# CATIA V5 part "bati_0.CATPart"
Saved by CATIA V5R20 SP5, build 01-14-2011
Part number: bati_0
Publications: "largeur_barre_7", "x_hauteur", "épaisseur bati"
Bounding box of the stored display mesh (mm): x -70 to 110, y -137 to 15, z 0 to 249.913
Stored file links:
  M:\EU_thinkMotion\IAO_2010\iao\IAO_MMS_Groupe2\IAO_MMS_Groupe2\sdubois\sdubois\sdubois\IAO_mecanisme\bati_0.CATPart
  M:\EU_thinkMotion\IAO_2010\iao\IAO_MMS_Groupe2\IAO_MMS_Groupe2\sdubois\sdubois\sdubois\IAO_mecanisme\assembage final.CATProduct
  M:\EU_thinkMotion\IAO_2010\iao\IAO_MMS_Groupe2\IAO_MMS_Groupe2\sdubois\sdubois\sdubois\IAO_mecanisme\squelette_bati.CATPart
  C:\Users\User\Desktop\IAO mécanisme\ancien\bati.CATPart
  M:\EU_thinkMotion\IAO_2010\iao\IAO_MMS_Groupe2\IAO_MMS_Groupe2\sdubois\sdubois\sdubois\IAO_mecanisme\squelette_7.CATPart
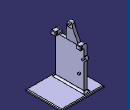
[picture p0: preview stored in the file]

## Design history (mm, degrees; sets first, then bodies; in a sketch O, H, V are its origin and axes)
Parameters
  largeur_barre = 6 mm
  x_hauteur = 20 mm
  `épaisseur bati` = 12 mm
External parameters (linked from other documents)
  `External.diamètre pivot en D` = 8 mm
  `External.diamètre pivot en A` = 8 mm
  `External.diamètre pivot en H` = 8 mm
Set1
  Plane1 to Plane5: linked copy from another document
  Point1 to Point3: linked copy from another document
  Plane6: linked copy from another document
  Plane7: linked copy from another document
  Point4: linked copy from another document
Body1 (main body)
  Sketch1 on Plane1, origin (0, 0, 0), H (0, 1, 0), V (0, 0, 1)
    line L1 (-137, 0) -> (15, 0)
    line L2 (-137, 0) -> (-137, 8)
    line L3 (-137, 8) -> (-122, 8)
    line L4 (0, 8) -> (15, 8)
    line L5 (15, 8) -> (15, 0)
    construction line L6 through (-77.2527, 0) direction (1, 0)
    line L7 (-122, 168) -> (-76, 168)
    line L8 (0, 168) -> (-22, 168)
    line L9 (0, 8) -> (0, 168)
    arc A1 centre (-49, 240) radius 10 from (-58.6074, 242.7746) to (-39.6859, 243.6397) cw
    point P1 (-22, 168)
    point P2 (-22, 168)
    line L10 (-122, 8) -> (-122, 168)
    point P3 (-49, 240)
    point P4 (0, 0)
    construction line L11 through (0, 0) direction (0, 1)
    line L12 (-22, 168) -> (-39.6859, 243.6397)
    line L13 (-76, 168) -> (-58.6074, 242.7746)
    reference intersected line E1 through (0, 0) direction (0, 1) from Plane2
    reference intersected line E2 through (0, 0) direction (-1, 0) from Plane3
    reference intersected line E3 through (0, 0) direction (-1, 0) from Plane3
    length L1 = 152
    length L2 = 8
    length L3 = 15
    length L4 = 15
    length L5 = 8
    distance L1 L6 = 0
    length L7 = 46
    length L8 = 22
    angle L4 L5 = 90
    angle L5 L1 = 90
    radius A1 = 10
    distance P2 P1 = 0
    angle L2 L3 = 90
    angle L2 L1 = 90
    angle L10 L3 = 90
    distance P3 L1 = 240 {= 220mm+x_hauteur}
    distance L8 L1 = 168 {= 148mm+x_hauteur}
    distance L7 L1 = 168 {= 148mm+x_hauteur}
    distance P3 L9 = 49
    distance E1 L9 = 0
    distance E2 L1 = 0
    parallelism: L7 L8, L8 E3
  Sketch2 on Plane2, origin (0, 0, 0), H (-1, 0, 0), V (0, 0, 1)
    line L1 (70, 8) -> (70, 0)
    line L2 (-110, 0) -> (70, 0)
    line L3 (0, 8) -> (-110, 8)
    line L4 (0, 168) -> (0, 8)
    line L5 (12, 8) -> (12, 168)
    line L6 (-12, 250) -> (-12, 228)
    line L7 (0, 228) -> (0, 250)
    line L8 (-110, 8) -> (-110, 0)
    line L9 (-12, 250) -> (0, 250)
    construction line L10 through (0, 0) direction (1, 0)
    construction line L11 through (0, 0) direction (0, 1)
    line L12 (70, 8) -> (12, 8)
    line L13 (12, 168) -> (0, 228)
    line L14 (-12, 228) -> (0, 168)
    reference intersected line E1 through (0, 0) direction (0, -1) from Plane1
    reference intersected line E2 through (0, 0) direction (-1, 0) from Plane3
    length L1 = 8
    distance L3 L2 = 8
    distance L5 L4 = 12 {= `épaisseur bati`}
    length L6 = 22
    length L5 = 160 {= 140mm+x_hauteur}
    length L4 = 160 {= 140mm+x_hauteur}
    distance L6 L4 = 12 {= 2*largeur_barre}
    distance L7 L5 = 12 {= 2*largeur_barre}
    distance L4 L8 = 110
    distance L9 L2 = 250 {= 230mm+x_hauteur}
    distance L1 L8 = 180
    length L7 = 22
    distance L4 E1 = 0
    distance L2 E2 = 0
    parallelism: L14 L13
  SolidCombine1: FirstComponentDirection Sketch2, FirstComponentProfile Sketch2, SecondComponentDirection Sketch1, SecondComponentProfile Sketch1
  Sketch3 on face of SolidCombine1 from Sketch2.L4, origin (0, 0, 0), H (0, 1, 0), V (0, 0, 1)
    point P1 (0, 138.775)
    point P2 (0, 121.225)
    point P3 (-2, 130)
    arc A1 centre (-2, 130) radius 9 from (0, 138.775) to (0, 121.225) cw
    point P4 (0, 138.775)
    point P5 (0, 121.225)
    line L1 (0, 138.775) -> (0, 121.225)
    reference projected point E1 (-2, 130) from Point2
    reference projected line E2 (0, 148) -> (0, 8) from edge [face of SolidCombine1 from Sketch2.L4 | face of SolidCombine1 from Sketch1.L9]
    radius A1 = 9
    distance P3 E1 = 0
    distance L1 E2 = 0
    coincidence: P1 P4, P2 P5
  Pad1: profile Sketch3, direction (-1, 0, 0), length 12 {= `épaisseur bati`}
  SolidCombine2: FirstComponentDirection Sketch8, FirstComponentProfile Sketch8, SecondComponentDirection Sketch10, SecondComponentProfile Sketch10
  SolidCombine3: FirstComponentDirection Sketch9, FirstComponentProfile Sketch9, SecondComponentDirection Sketch8, SecondComponentProfile Sketch8
  Sketch4 on face of SolidCombine1, origin (0, 0, 0), H (-1, 0, 0), V (0, 0, 1)
    line L1 (-12, 171.5) -> (-12, 181.5)
    line L2 (-6, 181.5) -> (-6, 171.5)
    line L3 (-6, 171.5) -> (-12, 171.5)
    line L4 (-12, 181.5) -> (-6, 181.5)
    reference intersected line E1 through (0, 171.5) direction (-1, 0) from Plane4
    reference intersected line E2 through (0, 171.5) direction (-1, 0) from Plane6
    reference intersected line E3 through (-12, 0) direction (0, -1) from Plane7
    reference projected point E4 (-12, 181.5) from Point4
    reference projected line E5 (12, 168) -> (12, 185) from edge [face of Pad1 | face of SolidCombine1]
    distance L3 E1 = 0
    distance L4 E4 = 0
    distance L1 L2 = 6 {= largeur_barre}
    distance L1 E5 = 24 {= `épaisseur bati` +2*largeur_barre}
    parallelism: L4 L3, L3 E2, L1 E3
  Pocket1: profile Sketch4, direction (0, -1, 0), through (limit type 3)
  Sketch5 on face of SolidCombine1 from Sketch2.L6, origin (12, 0, 0), H (0, 1, 0), V (0, 0, 1)
    circle A1 centre (-49, 240) radius 4
    point P1 (-49, 240)
    reference projected point E1 (-49, 240) from Point1
    radius A1 = 4 {= `External.diamètre pivot en H` /2}
    distance P1 E1 = 0
  Pad2: profile Sketch5, direction (1, 0, 0), length 6 {= largeur_barre}
  Sketch6 on face of Pad1, origin (0, 0, 0), H (0, 1, 0), V (0, 0, 1)
    circle A1 centre (-2, 130) radius 4
    point P1 (-2, 130)
    reference projected point E1 (-2, 130) from Point2
    radius A1 = 4 {= `External.diamètre pivot en D` /2}
    distance P1 E1 = 0
  Pad3: profile Sketch6, direction (1, 0, 0), length 6 {= largeur_barre}
  Sketch7 on face of Pad1, origin (0, 0, 0), H (0, 1, 0), V (0, 0, 1)
    circle A1 centre (-18, 70) radius 4
    point P1 (-18, 70)
    reference projected point E1 (-18, 70) from Point3
    radius A1 = 4 {= `External.diamètre pivot en A` /2}
    distance P1 E1 = 0
  Pad4: profile Sketch7, direction (1, 0, 0), length 6 {= largeur_barre}
  Fillet1: radius 8, on edge [face of SolidCombine2 from Sketch10.L4 | face of Pad1]; edge [face of SolidCombine3 from Sketch8.L4 | face of Pad1]
  Fillet2: radius 2, on edge [face of SolidCombine2 from Sketch8.L1 | face of SolidCombine2 from Sketch10.L4]; edge [face of SolidCombine3 from Sketch8.L1 | face of SolidCombine3 from Sketch8.L4]; edge [face of SolidCombine3 from Sketch8.L3 | face of SolidCombine3 from Sketch8.L1]; edge [face of SolidCombine2 from Sketch10.L3 | face of SolidCombine2 from Sketch8.L1]
  Fillet3: radius 2, on edge [face of Pad1 from Sketch3.A1 | face of SolidCombine1]; edge [face of SolidCombine1 from Sketch1.L9 | face of Pad1 from Sketch3.A1]
  Fillet4: radius 7, on edge [face of SolidCombine1 | face of Pad1]; edge [face of SolidCombine1 from Sketch1.L9 | face of SolidCombine1]; edge [face of Pad1 | face of SolidCombine1]; edge [face of SolidCombine1 | face of SolidCombine1]
  Fillet5: radius 3, on edge [face of SolidCombine1 | face of SolidCombine1 from Sketch1.L5]; edge [face of SolidCombine1 from Sketch2.L8 | face of SolidCombine1]; edge [face of SolidCombine1 from Sketch1.L2 | face of SolidCombine1]; edge [face of SolidCombine1 | face of SolidCombine1 from Sketch2.L1]
  Fillet6: radius 3, on edge [face of SolidCombine1 from Sketch1.L12 | face of SolidCombine1 from Sketch1.L8]; edge [face of SolidCombine1 from Sketch1.L7 | face of SolidCombine3 from Sketch9.L2]; edge [face of SolidCombine1 from Sketch1.L7 | face of SolidCombine1 from Sketch1.L13]
  Fillet7: radius 3, on edge [face of SolidCombine2 from Sketch10.L1 | face of SolidCombine1 from Sketch1.L8]
  Sketch8 on face of SolidCombine1 from Sketch1.L9, origin (0, 0, 0), H (-1, 0, 0), V (0, 0, 1)
    line L1 (-17, 168) -> (-17, 185)
    line L2 (12, 185) -> (12, 168)
    line L3 (12, 168) -> (-17, 168)
    line L4 (-17, 185) -> (12, 185)
    reference projected line E1 (14, 168) -> (0, 168) from edge [face of SolidCombine1 from Sketch1.L8 | face of SolidCombine1 from Sketch1.L9]
    reference projected line E2 (12, 8) -> (12, 148) from edge [face of Pad1 | face of SolidCombine1 from Sketch1.L9]
    distance L2 L1 = 29 {= 2*largeur_barre +`épaisseur bati` +5mm}
    distance L4 L3 = 17
    distance L3 E1 = 0
    distance L2 E2 = 0
  Sketch9 on face of Pad1, origin (-12, 0, 0), H (0, -1, 0), V (0, 0, 1)
    line L1 (122, 185) -> (122, 168)
    line L2 (106, 168) -> (106, 185)
    line L3 (122, 168) -> (106, 168)
    line L4 (106, 185) -> (122, 185)
    reference projected line E1 (122, 168) -> (76, 168) from edge [face of SolidCombine1 from Sketch1.L7 | face of SolidCombine1 from Sketch2.L5]
    reference projected line E2 (122, 8) -> (122, 148) from edge [face of SolidCombine1 from Sketch1.L10 | face of SolidCombine1 from Sketch2.L5]
    distance L2 L1 = 16
    distance L4 L3 = 17
    distance L3 E1 = 0
    distance L1 E2 = 0
  Sketch10 on face of Pad1, origin (-12, 0, 0), H (0, -1, 0), V (0, 0, 1)
    line L1 (16, 185) -> (16, 168)
    line L2 (0, 168) -> (0, 185)
    line L3 (16, 168) -> (0, 168)
    line L4 (0, 185) -> (16, 185)
    reference projected line E1 (22, 168) -> (0, 168) from edge [face of SolidCombine1 from Sketch1.L8 | face of SolidCombine1 from Sketch2.L5]
    reference projected line E2 (0, 8) -> (0, 148) from edge [face of Pad1 | face of SolidCombine1 from Sketch1.L9]
    distance L2 L1 = 16
    distance L4 L3 = 17
    distance L3 E1 = 0
    distance L2 E2 = 0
